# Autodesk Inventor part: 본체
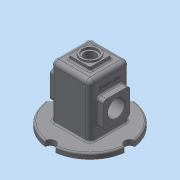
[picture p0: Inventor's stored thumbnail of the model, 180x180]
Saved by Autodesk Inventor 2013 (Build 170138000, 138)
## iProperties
Created: 2018-07
Part Number: 본체
Material: 일반
Document SubType Name: Modeling
Designer: Administrator
Density: 1 g/cm^3
Author: Administrator
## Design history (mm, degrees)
sketch "스케치1"
  geometry: L1 (-37, -37)-(37, -37); L2 (37, -37)-(37, 37); L3 (37, 37)-(-37, 37); L4 (-37, 37)-(-37, -37); L5 (-37, -37)-(37, 37); L6 (37, -37)-(-37, 37); 3 further points
  constraints: 12 end point, 3 midpoint, 2 parallel, 1 coincident, 1 horizontal, 1 perpendicular
  dimensions: "d0" = 74 distance of L3.end L2.end; "d1" = 74 distance of L2.end L1.end
extrude "돌출1" new body sketch "스케치1" distance "d2" = 110; taper "d3" = 0 deg
fillet "모깎기1" dims "d4" = 8
fillet "모깎기2" dims "d5" = 8
feature "쉘1" dims "d6" = 5
sketch "스케치2"
  geometry: L1 (-20, -20)-(20, -20); L2 (20, -20)-(20, 20); L3 (20, 20)-(-20, 20); L4 (-20, 20)-(-20, -20); L5 (-20, -20)-(20, 20); L6 (20, -20)-(-20, 20); 1 further point
  constraints: 12 end point, 2 midpoint, 2 parallel, 2 perpendicular, 1 horizontal
  dimensions: "d7" = 40 distance of L2.end L3.end
extrude "돌출2" join sketch "스케치2" distance "d9" = 7; taper "d10" = 0 deg
sketch "스케치3"
  geometry: C1 r 17.5 at (0, 0); 1 further point
  constraints: 1 centre point, 1 coincident
  dimensions: "d11" = 35 diameter of C1
extrude "돌출3" join sketch "스케치3" distance "d13" = 3; taper "d14" = 0 deg
hole "구멍1" diameter "d17" = 21; stored, may be unused: countersink angle "d21" = 90 deg, drill point angle "d23" = 118 deg; dims "d15" = 10, "d16" = 10, "d18" = 6, "d19" = 28, "d20" = 4, "d22" = 8
sketch "스케치4"
  geometry: L1 (-37, 29)-(-37, -29) reference; L2 (-29, -37)-(29, -37) reference; L3 (37, -29)-(37, 29) reference; L4 (29, 37)-(-29, 37) reference; A1 r 75 centre (0, 0) between (-74.333, -9.978) and (-9.978, -74.333); A2 r 10 centre (0, -75) between (9.978, -74.333) and (-9.978, -74.333); A3 r 10 centre (75, 0) between (74.333, -9.978) and (74.333, 9.978); A4 r 10 centre (0, 75) between (-9.978, 74.333) and (9.978, 74.333); A5 r 10 centre (-75, 0) between (-74.333, -9.978) and (-74.333, 9.978); A6 r 75 centre (0, 0) between (-74.333, 9.978) and (-74.333, -9.978); A7 r 10 centre (-75, 0) between (-74.333, 9.978) and (-74.333, -9.978); A8 r 75 centre (0, 0) between (-9.978, 74.333) and (-74.333, 9.978); A9 r 75 centre (0, 0) between (9.978, 74.333) and (-9.978, 74.333); A10 r 75 centre (0, 0) between (74.333, -9.978) and (74.333, 9.978); A11 r 75 centre (0, 0) between (74.333, 9.978) and (9.978, 74.333); A12 r 75 centre (0, 0) between (9.978, -74.333) and (74.333, -9.978); A13 r 75 centre (0, 0) between (-9.978, -74.333) and (9.978, -74.333); A14 r 10 centre (0, -75) between (-9.978, -74.333) and (9.978, -74.333); A15 r 10 centre (0, 75) between (9.978, 74.333) and (-9.978, 74.333); A16 r 10 centre (75, 0) between (74.333, 9.978) and (74.333, -9.978); A17 r 8 centre (-29, -29) between (-37, -29) and (-29, -37) reference; A18 r 8 centre (29, -29) between (29, -37) and (37, -29) reference; A19 r 8 centre (29, 29) between (37, 29) and (29, 37) reference; A20 r 8 centre (-29, 29) between (-29, 37) and (-37, 29) reference; 1 further point
  constraints: 47 point on circle, 16 centre point, 2 horizontal alignment, 2 vertical alignment, 1 coincident
  dimensions: "d24" = 150 diameter of A1; "d26" = 10 radius of A2; "d27" = 10 radius of A3; "d28" = 10 radius of A4; "d29" = 10 radius of A5
extrude "돌출4" join sketch "스케치4" distance "d30" = 10; taper "d31" = 0 deg
sketch "스케치5"
  geometry: L1 (54, -72)-(4, -72); L2 (4, -72)-(4, -22); L3 (4, -22)-(54, -22); L4 (54, -22)-(54, -72); L5 (54, -72)-(4, -22); L6 (4, -72)-(54, -22); L7 (19.022, -102)-(38.978, -102) reference; L8 (103.333, -102)-(38.978, -102) reference; 4 further points
  constraints: 12 end point, 4 midpoint, 2 parallel, 2 perpendicular, 1 horizontal, 1 vertical alignment
  dimensions: "d32" = 50 distance of L2.end L3.end; "d34" = 55 distance from line of L8 point (29, -47)
extrude "돌출5" join sketch "스케치5" distance "d35" = 13; taper "d36" = 0 deg
sketch "스케치6"
  geometry: L1 (58, 0)-(0, 0) reference; L2 (103.333, 0)-(38.978, 0) reference; C1 r 25 at (29, 55); 2 further points
  constraints: 1 centre point, 1 midpoint, 1 vertical alignment
  dimensions: "d37" = 55 distance from line of L2 C1.centre; "d38" = 50 diameter of C1
extrude "돌출6" join sketch "스케치6" distance "d39" = 7; taper "d40" = -20 deg
sketch "스케치7"
  geometry: L1 (103.333, -102)-(38.978, -102) reference; L2 (0, -102)-(58, -102) reference; 3 further points
  constraints: 1 midpoint, 1 vertical alignment
  dimensions: "d41" = 55 distance from line of L1 point (29, -47)
hole "구멍2" sketch "스케치7" at (29, -47) diameter "d42" = 32; stored, may be unused: countersink angle "d46" = 90 deg, drill point angle "d48" = 118 deg; dims "d43" = 6, "d44" = 28, "d45" = 4, "d47" = 8
fillet "모깎기3" dims "d49" = 6
sketch "스케치8"
  geometry: A1 r 6 centre (48, -28) between (54, -28) and (48, -22) reference; A2 r 6 centre (10, -28) between (10, -22) and (4, -28) reference; A3 r 6 centre (10, -66) between (4, -66) and (10, -72) reference; A4 r 6 centre (48, -66) between (48, -72) and (54, -66) reference; 5 further points
  constraints: 4 coincident
hole "구멍3" sketch "스케치8" at (10, -28), (10, -66), (48, -66), (48, -28) diameter "d50" = 3.242; stored, may be unused: countersink angle "d54" = 90 deg, drill point angle "d56" = 118 deg; dims "d51" = 8, "d52" = 28, "d53" = 4, "d55" = 10
sketch "스케치9"
  geometry: A1 r 6 centre (6, 38) between (6, 44) and (0, 38) reference; A2 r 6 centre (6, 0) between (0, 0) and (6, -6) reference; A3 r 6 centre (44, 0) between (44, -6) and (50, 0) reference; A4 r 6 centre (44, 38) between (50, 38) and (44, 44) reference; 5 further points
  constraints: 4 coincident
hole "구멍4" sketch "스케치9" at (6, 38), (6, 0), (44, 0), (44, 38) diameter "d57" = 3.242; stored, may be unused: countersink angle "d61" = 90 deg, drill point angle "d63" = 118 deg; dims "d58" = 8, "d59" = 28, "d60" = 4, "d62" = 10
sketch "스케치10"
  geometry: L1 (46.5, 18)-(11.5, 18) reference; L2 (66, -92)-(66, 0) reference; 2 further points
  constraints: 1 other
  dimensions: "d64" = 30 distance from line of L1 point (29, -12); "d65" = 37 distance from line of L2 point (29, -12)
feature "엠보싱1" sketch "스케치10" dims "d0" = 74, "d1" = 74, "d66" = 0.5, "d67" = 0
fillet "모깎기4" dims "d68" = 3
fillet "모깎기5" dims "d69" = 3
chamfer "모따기1" distance "d70" = 1; stored, may be unused: second distance "d71" = 2, angle "d72" = 45 deg
node "솔리드1"
mirror "대칭1"
